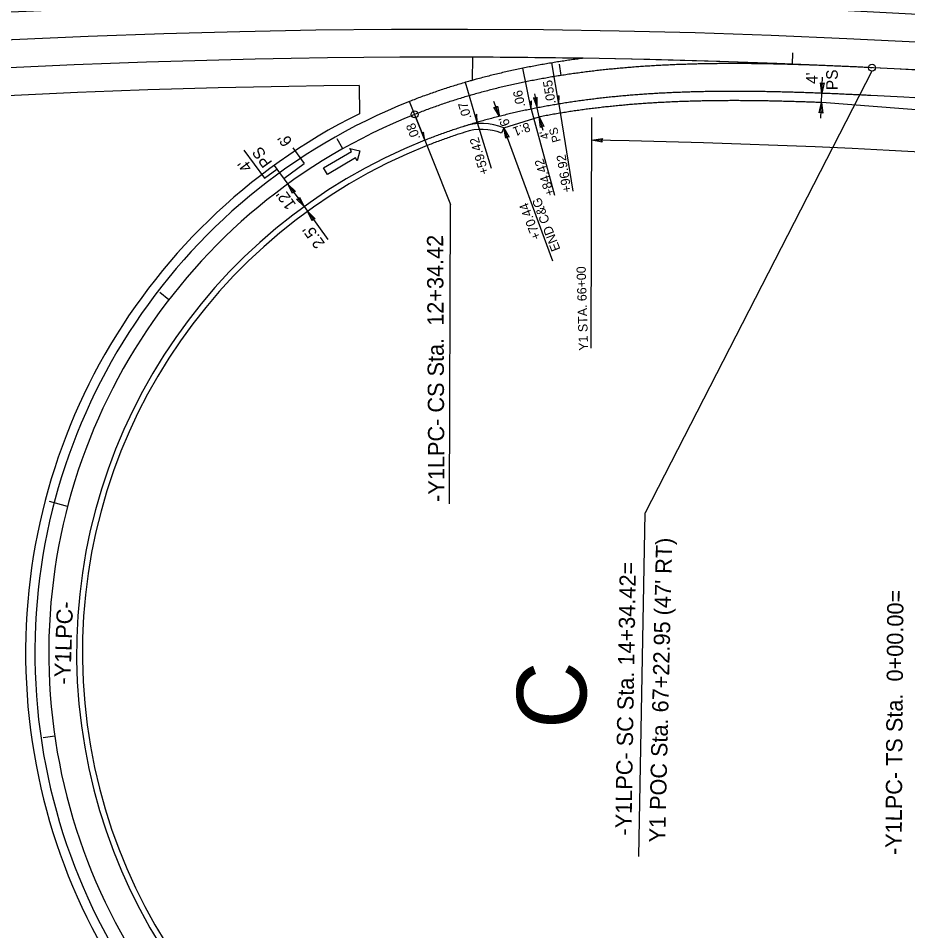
# Model space of a CAD drawing. Extents: x 2389694 to 2405615, y 546931 to 573532.
# Drawn here: x 2394645.3 to 2395029.1, y 553830.9 to 554224.7 of the extents above; entities that cross this region are included whole.
import ezdxf

# ---------------------------------------------------------------- set-up
doc = ezdxf.new("R2010")
doc.units = 0
for name, color, linetype in [('Prop Cable Guiderail Double Face', 7, 'Continuous'), ('Prop Conc 2ft 6in Curb and Gutter', 7, 'Continuous'), ('Prop Dimension', 7, 'Continuous'), ('Prop Dimension Text', 7, 'Continuous'), ('Prop DSN Text', 7, 'Continuous'), ('Prop EOT', 7, 'Continuous'), ('Prop Horizontal Alignment', 7, 'Continuous'), ('Prop Horizontal Alignment Curve and Spiral Data', 7, 'Continuous'), ('Prop Horizontal Alignment Tick Large', 7, 'Continuous'), ('Prop Horizontal Alignment Tick Small', 7, 'Continuous'), ('Prop Lane Arrow Through CELL', 7, 'Continuous'), ('Prop Lane Lines', 7, 'Continuous'), ('Prop Super Arrow 1 Lane CELL', 7, 'Continuous'), ('Prop Superelevation Label', 7, 'Continuous')]:
    doc.layers.add(name, color=color, linetype=linetype)

msp = doc.modelspace()

# ---------------------------------------------------------------- linework, layer by layer
at = {"layer": 'Prop Cable Guiderail Double Face'}
msp.add_arc((2394828.31, 550434.92), 3824, 87.04844, 123.9393, dxfattribs=at)
at = {"layer": 'Prop Conc 2ft 6in Curb and Gutter'}
msp.add_line((2394854.78, 554177.44), (2394853.84, 554175.13), dxfattribs=at)
for centre, radius, start, end in [((2394845.37, 554154.28), 25, 67.8911, 109.2791), ((2394845.37, 554154.28), 22.5, 67.8914, 109.2791), ((2394908.45, 553950.81), 235.5, 111.6201, 325.7741)]:
    msp.add_arc(centre, radius, start, end, dxfattribs=at)
msp.add_spline([(2394837.94, 554175.52), (2394833.65, 554174.13), (2394831.24, 554173.3), (2394828.83, 554172.45), (2394826.43, 554171.57), (2394824.05, 554170.67), (2394821.61, 554169.72)], degree=3, dxfattribs=at)
at = {"layer": 'Prop Dimension'}
for p, q in [((2394992.07, 554192.34), (2394992.34, 554199.25)), ((2394868.07, 554192.07), (2394869.26, 554186.07)), ((2394991.92, 554188.35), (2394992.07, 554192.34)), ((2394852.89, 554182.32), (2394850.53, 554188.74)), ((2394878.5, 554187.69), (2394884.67, 554150.09)), ((2394991.66, 554181.55), (2394991.92, 554188.35)), ((2394866.64, 554185.51), (2394876.65, 554148.32)), ((2394843.33, 554179.78), (2394849.38, 554160.08)), ((2394871.78, 554176.23), (2394870.13, 554182.12)), ((2394892.69, 554135.45), (2394892.87, 554181.82)), ((2394875.91, 554119.91), (2394854.81, 554177.41)), ((2394742.69, 554167.84), (2394751.5, 554155.7)), ((2394763.74, 554168.85), (2394768.71, 554162)), ((2394755.74, 554161.24), (2394758.09, 554158)), ((2394759.85, 554155.58), (2394768.71, 554162)), ((2394751.5, 554155.7), (2394756.92, 554159.62)), ((2394758.09, 554158), (2394761.61, 554153.15)), ((2394761.61, 554153.15), (2394768.66, 554143.44)), ((2394768.66, 554143.44), (2394770.13, 554141.41)), ((2394770.13, 554141.41), (2394778.94, 554129.27)), ((2394892.49, 554082.35), (2394892.69, 554135.45))]:
    msp.add_line(p, q, dxfattribs=at)
for points in [[(2394993.02, 554196.81), (2394992.07, 554192.34), (2394991.45, 554196.9), (2394992.23, 554196.29)], [(2394867.63, 554190.33), (2394869.26, 554186.07), (2394869.17, 554190.66), (2394868.49, 554189.94)], [(2394990.97, 554183.88), (2394991.92, 554188.35), (2394992.55, 554183.8), (2394991.77, 554184.4)], [(2394852.06, 554186.81), (2394852.89, 554182.32), (2394850.58, 554186.29), (2394851.53, 554186.03)], [(2394870.6, 554177.58), (2394870.13, 554182.12), (2394872.12, 554177.98), (2394871.2, 554178.32)], [(2394855.63, 554172.92), (2394854.81, 554177.41), (2394857.12, 554173.44), (2394856.17, 554173.71)], [(2394897.32, 554171.21), (2394892.84, 554172.07), (2394897.37, 554172.79), (2394896.79, 554172)], [(2394763.63, 554149.05), (2394761.61, 554153.15), (2394764.92, 554149.96), (2394763.93, 554149.95)], [(2394766.65, 554147.53), (2394768.66, 554143.44), (2394765.36, 554146.63), (2394766.34, 554146.63)], [(2394772.15, 554137.32), (2394770.13, 554141.41), (2394773.44, 554138.22), (2394772.45, 554138.22)]]:
    msp.add_lwpolyline(points, close=True, dxfattribs=at)
msp.add_arc((2394828.31, 550434.92), 3737.71, 73.27853, 89.01084, dxfattribs=at)
at = {"layer": 'Prop DSN Text'}
msp.add_line((2394870.13, 554182.12), (2394869.26, 554186.07), dxfattribs=at)
at = {"layer": 'Prop EOT'}
for p, q in [((2394841.25, 554207.89), (2394841.22, 554197.89)), ((2394792.41, 554195.74), (2394792.52, 554183.54)), ((2395129.66, 554177.8), (2394992.08, 554188.34)), ((2394854.78, 554177.44), (2394870.13, 554182.12))]:
    msp.add_line(p, q, dxfattribs=at)
for centre, radius, start, end in [((2394865.6, 554590.75), 1087, 256.52302, 12.63033), ((2394865.6, 554590.75), 1063, 256.52302, 12.63033), ((2394828.31, 550434.92), 3879, 67.475, 106.78848), ((2394828.31, 550434.92), 3867, 59.69891, 109.59769), ((2394828.31, 550434.92), 3843, 59.69891, 123.9393), ((2394828.31, 550434.92), 3839, 59.69891, 123.9393), ((2394828.31, 550434.92), 3801, 59.69891, 123.9393), ((2394828.31, 550434.92), 3797, 59.69891, 123.9393), ((2394828.31, 550434.92), 3773, 89.80344, 120.03622), ((2394828.31, 550434.92), 3761, 90.54697, 120.03622), ((2394828.31, 550434.92), 3761, 73.27853, 87.18326), ((2394908.45, 553950.81), 256, 111.6201, 325.7741), ((2394908.45, 553950.81), 260, 116.4784, 325.7741), ((2394908.45, 553950.81), 238, 111.6201, 325.7741)]:
    msp.add_arc(centre, radius, start, end, dxfattribs=at)
for points in [[(2394841.22, 554197.9), (2394840.3, 554197.64), (2394837.64, 554196.87), (2394835, 554196.08), (2394832.36, 554195.27), (2394829.73, 554194.42), (2394827.11, 554193.55), (2394824.49, 554192.66), (2394821.89, 554191.74), (2394819.29, 554190.79), (2394816.7, 554189.81), (2394814.15, 554188.81)], [(2395013.14, 554191.37), (2395010.44, 554191.5), (2395007.75, 554191.63), (2395005.07, 554191.76), (2395002.38, 554191.88), (2394999.7, 554192), (2394997.01, 554192.12), (2394994.33, 554192.23), (2394991.65, 554192.34), (2394988.98, 554192.44), (2394986.3, 554192.54), (2394983.62, 554192.63), (2394980.95, 554192.71), (2394978.28, 554192.79), (2394975.61, 554192.86), (2394972.94, 554192.93), (2394970.27, 554192.99), (2394967.6, 554193.04), (2394964.94, 554193.08), (2394962.27, 554193.11), (2394959.61, 554193.14), (2394956.95, 554193.15), (2394954.29, 554193.16), (2394951.63, 554193.15), (2394948.98, 554193.14), (2394946.32, 554193.11), (2394943.67, 554193.08), (2394941.02, 554193.03), (2394938.37, 554192.97), (2394935.73, 554192.9), (2394933.08, 554192.82), (2394930.44, 554192.72), (2394927.8, 554192.62), (2394925.16, 554192.49), (2394922.53, 554192.36), (2394919.89, 554192.21), (2394917.26, 554192.04), (2394914.63, 554191.87), (2394912.01, 554191.67), (2394909.39, 554191.46), (2394906.77, 554191.24), (2394904.15, 554191), (2394901.53, 554190.74), (2394898.92, 554190.47), (2394896.32, 554190.18), (2394893.71, 554189.87), (2394891.12, 554189.54), (2394888.52, 554189.2), (2394885.93, 554188.84), (2394883.34, 554188.46), (2394880.76, 554188.06), (2394878.18, 554187.64), (2394875.61, 554187.2), (2394873.04, 554186.74), (2394870.48, 554186.27), (2394867.92, 554185.77), (2394865.37, 554185.25), (2394862.83, 554184.71), (2394860.29, 554184.15), (2394857.76, 554183.56), (2394855.23, 554182.96), (2394852.71, 554182.33), (2394850.2, 554181.68), (2394847.7, 554181.01), (2394845.2, 554180.32), (2394842.72, 554179.6), (2394840.24, 554178.86), (2394837.77, 554178.1), (2394835.31, 554177.31), (2394832.86, 554176.5), (2394830.41, 554175.66), (2394827.98, 554174.8), (2394825.56, 554173.91), (2394823.15, 554173), (2394820.7, 554172.04)], [(2394992.08, 554188.32), (2394991.5, 554188.34), (2394988.83, 554188.44), (2394986.16, 554188.54), (2394983.49, 554188.63), (2394980.83, 554188.71), (2394978.16, 554188.79), (2394975.5, 554188.86), (2394972.84, 554188.93), (2394970.19, 554188.99), (2394967.53, 554189.04), (2394964.88, 554189.08), (2394962.23, 554189.11), (2394959.58, 554189.14), (2394956.93, 554189.15), (2394954.29, 554189.16), (2394951.65, 554189.15), (2394949.01, 554189.14), (2394946.37, 554189.11), (2394943.73, 554189.08), (2394941.1, 554189.03), (2394938.47, 554188.97), (2394935.84, 554188.9), (2394933.22, 554188.82), (2394930.59, 554188.73), (2394927.97, 554188.62), (2394925.36, 554188.5), (2394922.74, 554188.36), (2394920.13, 554188.22), (2394917.52, 554188.05), (2394914.92, 554187.88), (2394912.31, 554187.68), (2394909.72, 554187.48), (2394907.12, 554187.25), (2394904.53, 554187.02), (2394901.94, 554186.76), (2394899.35, 554186.49), (2394896.77, 554186.2), (2394894.2, 554185.9), (2394891.63, 554185.58), (2394889.06, 554185.24), (2394886.5, 554184.88), (2394883.94, 554184.5), (2394881.39, 554184.11), (2394878.84, 554183.69), (2394876.3, 554183.26), (2394873.76, 554182.81), (2394871.23, 554182.34), (2394870.13, 554182.12)], [(2394992.08, 554188.32), (2394991.5, 554188.34), (2394988.83, 554188.44), (2394986.16, 554188.54), (2394983.49, 554188.63), (2394980.83, 554188.71), (2394978.16, 554188.79), (2394975.5, 554188.86), (2394972.84, 554188.93), (2394970.19, 554188.99), (2394967.53, 554189.04), (2394965.45, 554189.07)]]:
    msp.add_spline(points, degree=3, dxfattribs=at)
at = {"layer": 'Prop Horizontal Alignment'}
for centre, radius, start, end in [((2394865.6, 554590.75), 1075, 256.52302, 12.63033), ((2394828.31, 550434.92), 3820, 59.69891, 123.9393), ((2394908.45, 553950.81), 250, 111.6201, 325.7741)]:
    msp.add_arc(centre, radius, start, end, dxfattribs=at)
msp.add_spline([(2395013.72, 554203.36), (2395011.02, 554203.49), (2395008.32, 554203.62), (2395005.62, 554203.75), (2395002.92, 554203.87), (2395000.22, 554203.99), (2394997.52, 554204.11), (2394994.82, 554204.22), (2394992.12, 554204.33), (2394989.42, 554204.43), (2394986.72, 554204.53), (2394984.02, 554204.62), (2394981.32, 554204.71), (2394978.62, 554204.79), (2394975.91, 554204.86), (2394973.21, 554204.93), (2394970.51, 554204.98), (2394967.81, 554205.03), (2394965.11, 554205.08), (2394962.4, 554205.11), (2394959.7, 554205.14), (2394957, 554205.15), (2394954.3, 554205.16), (2394951.59, 554205.15), (2394948.89, 554205.14), (2394946.19, 554205.11), (2394943.49, 554205.08), (2394940.78, 554205.03), (2394938.08, 554204.97), (2394935.38, 554204.9), (2394932.68, 554204.81), (2394929.98, 554204.72), (2394927.28, 554204.6), (2394924.58, 554204.48), (2394921.88, 554204.34), (2394919.18, 554204.19), (2394916.48, 554204.02), (2394913.79, 554203.84), (2394911.09, 554203.64), (2394908.4, 554203.42), (2394905.7, 554203.19), (2394903.01, 554202.94), (2394900.32, 554202.68), (2394897.63, 554202.4), (2394894.95, 554202.1), (2394892.26, 554201.78), (2394889.58, 554201.44), (2394886.9, 554201.09), (2394884.23, 554200.72), (2394881.55, 554200.32), (2394878.88, 554199.91), (2394876.21, 554199.48), (2394873.55, 554199.02), (2394870.89, 554198.55), (2394868.23, 554198.05), (2394865.58, 554197.54), (2394862.93, 554197), (2394860.29, 554196.44), (2394857.65, 554195.85), (2394855.01, 554195.25), (2394852.39, 554194.62), (2394849.76, 554193.97), (2394847.15, 554193.29), (2394844.54, 554192.59), (2394841.93, 554191.86), (2394839.33, 554191.12), (2394836.75, 554190.34), (2394834.16, 554189.54), (2394831.59, 554188.72), (2394829.02, 554187.87), (2394826.47, 554186.99), (2394823.92, 554186.09), (2394821.38, 554185.16), (2394818.85, 554184.21), (2394816.33, 554183.22)], degree=3, dxfattribs=at)
at = {"layer": 'Prop Horizontal Alignment Curve and Spiral Data'}
for p, q in [((2395013.65, 554201.86), (2394915.8, 554011.26)), ((2394816.89, 554181.83), (2394831.74, 554144.35)), ((2394831.4, 554015.13), (2394831.74, 554144.35)), ((2394913.09, 553862.97), (2394915.8, 554011.26))]:
    msp.add_line(p, q, dxfattribs=at)
for centre in [(2395013.72, 554203.36), (2394816.33, 554183.22)]:
    msp.add_circle(centre, 1.5, dxfattribs=at)
at = {"layer": 'Prop Horizontal Alignment Tick Large'}
msp.add_line((2394666.58, 554014.06), (2394658.84, 554016.08), dxfattribs=at)
at = {"layer": 'Prop Horizontal Alignment Tick Small'}
for p, q in [((2394979.33, 554204.77), (2394979.47, 554209.76)), ((2394879.58, 554200.02), (2394878.81, 554204.96)), ((2394785.31, 554168.38), (2394782.84, 554172.73)), ((2394710.3, 554103.25), (2394706.34, 554106.3)), ((2394661.04, 553914.88), (2394656.1, 553914.16))]:
    msp.add_line(p, q, dxfattribs=at)
at = {"layer": 'Prop Lane Arrow Through CELL'}
for p, q in [((2394789.09, 554167.26), (2394788.33, 554168.55)), ((2394788.33, 554168.55), (2394792.62, 554167.48)), ((2394777.04, 554160.14), (2394789.09, 554167.26)), ((2394790.77, 554164.41), (2394778.71, 554157.3)), ((2394791.53, 554163.12), (2394790.77, 554164.41)), ((2394792.62, 554167.48), (2394791.53, 554163.12)), ((2394778.71, 554157.3), (2394777.04, 554160.14))]:
    msp.add_line(p, q, dxfattribs=at)
at = {"layer": 'Prop Lane Lines'}
for radius, start, end in [(3855, 59.69891, 123.9393), (3785, 59.69891, 123.9393), (3773, 89.07696, 89.80344), (3773, 68.81433, 89.07696), (3773, 59.69891, 88.86914)]:
    msp.add_arc((2394828.31, 550434.92), radius, start, end, dxfattribs=at)
msp.add_spline([(2394888.72, 554207.38), (2394886.09, 554207.04), (2394883.37, 554206.66), (2394880.66, 554206.26), (2394877.94, 554205.84), (2394875.23, 554205.4), (2394872.52, 554204.93), (2394869.81, 554204.45), (2394867.11, 554203.95), (2394864.41, 554203.42), (2394861.71, 554202.87), (2394859.02, 554202.3), (2394856.33, 554201.71), (2394853.64, 554201.09), (2394850.96, 554200.45), (2394848.29, 554199.78), (2394845.62, 554199.09), (2394842.95, 554198.38), (2394841.22, 554197.9)], degree=3, dxfattribs=at)
at = {"layer": 'Prop Super Arrow 1 Lane CELL'}
for p, q in [((2394866.64, 554185.51), (2394863.06, 554203.15)), ((2394878.5, 554187.69), (2394875.57, 554205.45)), ((2394843.33, 554179.78), (2394838.3, 554197.06)), ((2394820.76, 554172.07), (2394814.12, 554188.8))]:
    msp.add_line(p, q, dxfattribs=at)
for points in [[(2394866.64, 554185.51), (2394866.73, 554189.1), (2394866.06, 554188.4)], [(2394878.5, 554187.69), (2394878.72, 554191.28), (2394878.02, 554190.6)], [(2394843.33, 554179.78), (2394843.12, 554183.37), (2394842.51, 554182.61)], [(2394820.76, 554172.07), (2394820.21, 554175.62), (2394819.67, 554174.81)]]:
    msp.add_lwpolyline(points, close=True, dxfattribs=at)

# ---------------------------------------------------------------- texts
at = {"layer": 'Prop Dimension Text'}
for s, height, rotation, p in [("4'", 5, 90.1385, (2394990.29, 554196.37)), ('PS', 5, 90.1385, (2394998.94, 554193.69)), ("6'", 4, 111.0203, (2394857.59, 554178.96)), ('8:1', 4, 199.8065, (2394865.35, 554179.91)), ('PS', 3.624, 105.7354, (2394879.45, 554171.73)), ("6'", 5, 125.9678, (2394763.81, 554171.56)), ('+59.42', 4, 106.2255, (2394848.41, 554157.87)), ("4'", 3.624, 105.7354, (2394874.55, 554173)), ('PS', 5, 125.9678, (2394755.12, 554162.52)), ('+84.42', 4, 107.7804, (2394876.79, 554148.7)), ('+96.92', 4, 99.3865, (2394884.11, 554149.87)), ("4'", 5, 125.9678, (2394746.54, 554160.52)), ("12'", 5, 125.9677, (2394765.35, 554144.33)), ('+70.44', 4, 111.0203, (2394870.95, 554130.04)), ('END C&G', 4, 111.0203, (2394879.31, 554125.02)), ("2.5'", 5, 125.9678, (2394777.83, 554127.59)), ('Y1 STA. 66+00', 4, 91.6835, (2394891.21, 554081.28))]:
    msp.add_text(s, height=height, rotation=rotation, dxfattribs=at).set_placement(p)
at = {"layer": 'Prop Horizontal Alignment Curve and Spiral Data'}
for s, height, rotation, p in [('-Y1LPC- CS Sta.  12+34.42', 7, 90.3046, (2394829.25, 554016.03)), ("Y1 POC Sta. 67+22.95 (47' RT)", 7, 88.6559, (2394924.46, 553868.88)), ('-Y1LPC- SC Sta. 14+34.42=', 7, 89.0394, (2394909.87, 553871.94)), ('-Y1LPC- TS Sta.  0+00.00=', 7, 89.5902, (2395026.48, 553863.53)), ('-Y1LPC-', 7, 88.0614, (2394667.75, 553937.01)), ('C', 30, 90, (2394890.45, 553918.06))]:
    msp.add_text(s, height=height, rotation=rotation, dxfattribs=at).set_placement(p)
at = {"layer": 'Prop Superelevation Label'}
for s, rotation, p in [('.055', 99.3865, (2394877.26, 554188.02)), ('.06', 101.499, (2394864.1, 554186.7)), ('.07', 106.2255, (2394840.91, 554181.78)), ('.08', 111.6208, (2394818.9, 554172.99))]:
    msp.add_text(s, height=4, rotation=rotation, dxfattribs=at).set_placement(p)

doc.saveas('drawing.dxf')
